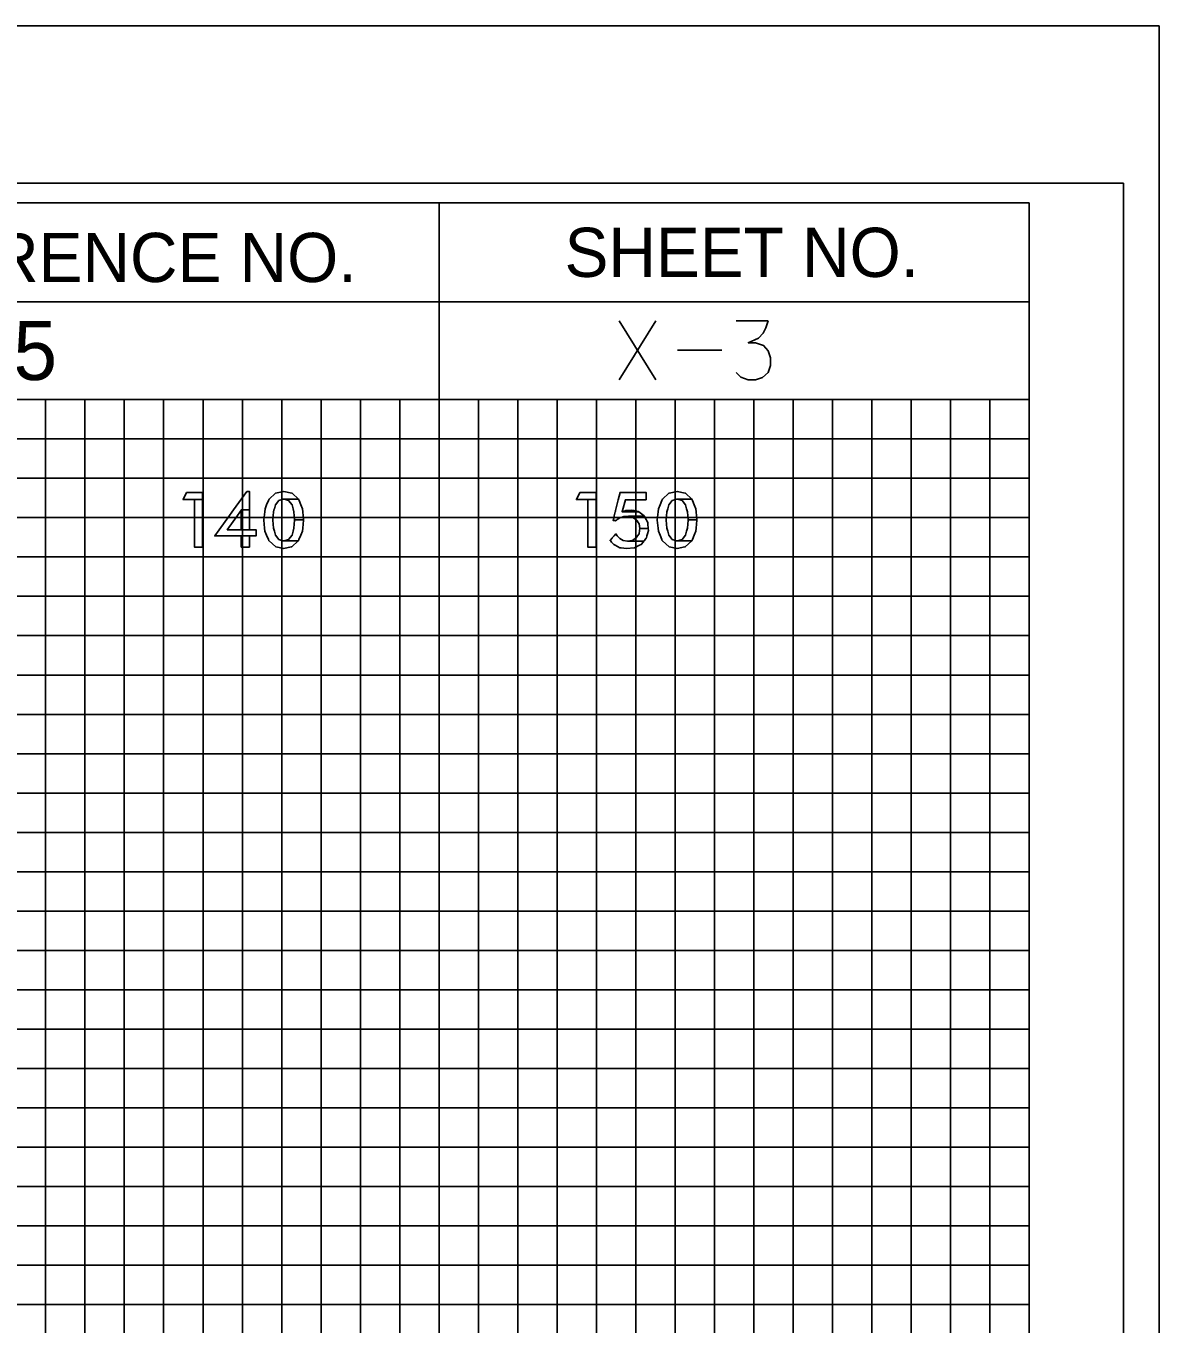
# Model space of a CAD drawing. Extents: x -13 to 323, y -5 to 1431.
# Drawn here: x 294.5 to 323.3, y 401.5 to 434.5 of the extents above; entities that cross this region are included whole.
import ezdxf

# ---------------------------------------------------------------- set-up
doc = ezdxf.new("R2010")
doc.units = 0
for name, color, linetype in [('Prop XS Offset Labels', 7, 'Continuous'), ('Prop XS Project Number', 7, 'Continuous'), ('Prop XS Sheet Number', 7, 'Continuous'), ('Sheet Cross Section CELL', 7, 'Continuous'), ('Sheet Cross Section Grid Major CELL', 7, 'Continuous'), ('Sheet Cross Section Grid Middle CELL', 7, 'Continuous'), ('Sheet Cross Section Grid Minor 1 CELL', 7, 'Continuous'), ('Sheet Cross Section Grid Minor 2 CELL', 7, 'Continuous'), ('Sheet Cutting Line CELL', 7, 'Continuous'), ('Sheet DOT Grid CELL', 7, 'Continuous'), ('Sheet Plot Border Inside CELL', 7, 'Continuous'), ('Sheet Plot Border Outside CELL', 7, 'Continuous')]:
    doc.layers.add(name, color=color, linetype=linetype)

msp = doc.modelspace()

# ---------------------------------------------------------------- linework, layer by layer
at = {"layer": 'Prop XS Offset Labels'}
for points in [[(298.581, 422.641), (298.492, 422.459), (298.99, 422.459), (298.99, 422.641)], [(298.781, 422.459), (298.781, 421.25), (298.99, 421.25), (298.99, 422.459)], [(299.411, 421.693), (299.297, 421.534), (300.35, 421.534), (300.35, 421.693), (299.618, 421.693), (299.878, 422.059), (299.935, 422.139), (299.977, 422.199), (300.179, 422.199), (300.179, 422.668), (300.114, 422.668), (299.775, 422.199), (299.733, 422.139), (299.675, 422.059)], [(300.851, 421.255), (301.051, 421.214), (301.245, 421.255), (301.256, 421.257), (301.422, 421.409), (301.048, 421.409), (301.038, 421.411), (301.033, 421.413), (300.928, 421.442), (300.841, 421.555), (300.841, 421.556), (300.841, 421.556), (300.813, 421.657), (300.813, 421.659), (300.793, 421.732), (300.792, 421.736), (300.774, 421.939), (300.774, 421.941), (300.774, 421.943), (300.792, 422.145), (300.812, 422.222), (300.813, 422.224), (300.839, 422.322), (300.84, 422.325), (300.928, 422.44), (301.041, 422.469), (301.045, 422.47), (301.055, 422.473), (301.425, 422.473), (301.262, 422.622), (301.254, 422.624), (301.053, 422.668), (301.053, 422.668), (300.845, 422.624), (300.843, 422.622), (300.681, 422.473), (300.678, 422.47), (300.678, 422.469), (300.665, 422.44), (300.618, 422.325), (300.617, 422.322), (300.577, 422.224), (300.576, 422.222), (300.568, 422.145), (300.547, 421.943), (300.547, 421.941), (300.547, 421.939), (300.567, 421.736), (300.567, 421.732), (300.575, 421.659), (300.575, 421.657), (300.616, 421.556), (300.617, 421.555), (300.663, 421.442), (300.675, 421.413), (300.676, 421.411), (300.679, 421.409), (300.848, 421.257)], [(301.312, 422.145), (301.328, 421.943), (301.555, 421.943), (301.536, 422.145), (301.528, 422.222), (301.528, 422.224), (301.527, 422.224), (301.488, 422.322), (301.488, 422.322), (301.487, 422.325), (301.441, 422.44), (301.44, 422.44), (301.429, 422.469), (301.428, 422.47), (301.425, 422.473), (301.055, 422.473), (301.065, 422.47), (301.068, 422.469), (301.175, 422.44), (301.262, 422.325), (301.265, 422.322), (301.291, 422.224), (301.291, 422.222)], [(308.581, 422.641), (308.492, 422.459), (308.99, 422.459), (308.99, 422.641)], [(308.781, 422.459), (308.781, 421.25), (308.99, 421.25), (308.99, 422.459)], [(309.427, 421.94), (309.424, 421.928), (309.495, 421.928), (309.508, 421.94), (309.524, 421.954), (309.595, 421.997), (309.627, 422.007), (309.697, 422.029), (309.811, 422.035), (310.219, 422.035), (310.211, 422.05), (310.076, 422.145), (309.655, 422.145), (309.658, 422.158), (309.658, 422.158), (309.663, 422.178), (309.738, 422.456), (310.263, 422.456), (310.263, 422.641), (309.6, 422.641), (309.554, 422.456), (309.486, 422.178), (309.481, 422.158), (309.478, 422.145), (309.454, 422.05), (309.451, 422.035), (309.449, 422.029), (309.444, 422.007), (309.441, 421.997), (309.431, 421.954)], [(310.851, 421.255), (311.051, 421.214), (311.245, 421.255), (311.256, 421.257), (311.422, 421.409), (311.048, 421.409), (311.038, 421.411), (311.033, 421.413), (310.928, 421.442), (310.841, 421.555), (310.841, 421.556), (310.841, 421.556), (310.813, 421.657), (310.813, 421.659), (310.793, 421.732), (310.792, 421.736), (310.774, 421.939), (310.774, 421.941), (310.774, 421.943), (310.792, 422.145), (310.812, 422.222), (310.813, 422.224), (310.839, 422.322), (310.84, 422.325), (310.928, 422.44), (311.041, 422.469), (311.045, 422.47), (311.055, 422.473), (311.425, 422.473), (311.262, 422.622), (311.254, 422.624), (311.053, 422.668), (311.053, 422.668), (310.845, 422.624), (310.843, 422.622), (310.681, 422.473), (310.678, 422.47), (310.678, 422.469), (310.665, 422.44), (310.618, 422.325), (310.617, 422.322), (310.577, 422.224), (310.576, 422.222), (310.568, 422.145), (310.547, 421.943), (310.547, 421.941), (310.547, 421.939), (310.567, 421.736), (310.567, 421.732), (310.575, 421.659), (310.575, 421.657), (310.616, 421.556), (310.617, 421.555), (310.663, 421.442), (310.675, 421.413), (310.676, 421.411), (310.679, 421.409), (310.848, 421.257)], [(311.312, 422.145), (311.328, 421.943), (311.555, 421.943), (311.536, 422.145), (311.528, 422.222), (311.528, 422.224), (311.527, 422.224), (311.488, 422.322), (311.488, 422.322), (311.487, 422.325), (311.441, 422.44), (311.44, 422.44), (311.429, 422.469), (311.428, 422.47), (311.425, 422.473), (311.055, 422.473), (311.065, 422.47), (311.068, 422.469), (311.175, 422.44), (311.262, 422.325), (311.265, 422.322), (311.291, 422.224), (311.291, 422.222)], [(299.97, 422.059), (299.97, 421.693), (300.179, 421.693), (300.179, 422.059), (300.179, 422.139), (300.179, 422.199), (299.977, 422.199), (299.973, 422.139)], [(309.692, 422.158), (309.655, 422.145), (310.076, 422.145), (310.058, 422.158), (309.961, 422.178), (309.75, 422.178)], [(309.888, 422.192), (309.75, 422.178), (309.96, 422.178), (309.888, 422.192)], [(301.058, 421.411), (301.048, 421.409), (301.422, 421.409), (301.425, 421.411), (301.426, 421.413), (301.438, 421.442), (301.485, 421.555), (301.485, 421.556), (301.527, 421.657), (301.528, 421.659), (301.535, 421.732), (301.535, 421.736), (301.555, 421.939), (301.556, 421.941), (301.555, 421.943), (301.328, 421.943), (301.328, 421.941), (301.328, 421.939), (301.312, 421.736), (301.312, 421.732), (301.292, 421.659), (301.291, 421.657), (301.264, 421.556), (301.263, 421.555), (301.175, 421.442), (301.063, 421.413)], [(309.424, 421.928), (309.482, 421.916), (309.495, 421.928)], [(310.083, 421.841), (310.105, 421.721), (310.318, 421.721), (310.307, 421.841), (310.307, 421.841), (310.303, 421.881), (310.284, 421.916), (310.278, 421.928), (310.271, 421.94), (310.263, 421.954), (310.24, 421.997), (310.235, 422.007), (310.223, 422.029), (310.219, 422.035), (309.811, 422.035), (309.838, 422.029), (309.928, 422.007), (309.942, 421.997), (310.003, 421.954), (310.024, 421.94), (310.031, 421.928), (310.038, 421.916), (310.059, 421.881)], [(311.058, 421.411), (311.048, 421.409), (311.422, 421.409), (311.425, 421.411), (311.426, 421.413), (311.438, 421.442), (311.485, 421.555), (311.485, 421.556), (311.527, 421.657), (311.528, 421.659), (311.535, 421.732), (311.535, 421.736), (311.555, 421.939), (311.556, 421.941), (311.555, 421.943), (311.328, 421.943), (311.328, 421.941), (311.328, 421.939), (311.312, 421.736), (311.312, 421.732), (311.292, 421.659), (311.291, 421.657), (311.264, 421.556), (311.263, 421.555), (311.175, 421.442), (311.063, 421.413)], [(299.97, 421.534), (299.97, 421.25), (300.179, 421.25), (300.179, 421.534)], [(309.626, 421.233), (309.762, 421.214), (309.959, 421.233), (309.968, 421.237), (310.091, 421.297), (310.091, 421.297), (310.141, 421.321), (310.185, 421.375), (310.204, 421.399), (309.793, 421.399), (309.683, 421.418), (309.682, 421.419), (309.679, 421.42), (309.596, 421.466), (309.586, 421.477), (309.58, 421.483), (309.58, 421.483), (309.529, 421.535), (309.497, 421.585), (309.497, 421.585), (309.451, 421.535), (309.404, 421.483), (309.399, 421.477), (309.39, 421.466), (309.348, 421.42), (309.347, 421.419), (309.348, 421.418), (309.363, 421.399), (309.382, 421.375), (309.445, 421.321), (309.474, 421.297), (309.598, 421.237)], [(309.9, 421.418), (309.793, 421.399), (310.204, 421.399), (310.22, 421.418), (310.221, 421.419), (310.222, 421.42), (310.222, 421.42), (310.259, 421.466), (310.268, 421.477), (310.27, 421.483), (310.284, 421.535), (310.299, 421.59), (310.322, 421.674), (310.318, 421.721), (310.105, 421.721), (310.097, 421.674), (310.082, 421.59), (310.047, 421.535), (310.014, 421.483), (310.004, 421.477), (309.987, 421.466), (309.913, 421.42), (309.905, 421.419)]]:
    msp.add_lwpolyline(points, close=True, dxfattribs=at)
at = {"layer": 'Prop XS Sheet Number'}
for p, q in [((309.575, 427), (310.508, 425.5)), ((310.508, 427), (309.575, 425.5)), ((312.551, 427), (313.366, 427)), ((311.063, 426.256), (312.185, 426.256))]:
    msp.add_line(p, q, dxfattribs=at)
msp.add_lwpolyline([(313.366, 427), (313.307, 426.823), (313.236, 426.693), (313.118, 426.563), (312.858, 426.445), (313.047, 426.445), (313.248, 426.374), (313.366, 426.244), (313.425, 426.067), (313.425, 425.866), (313.366, 425.689), (313.224, 425.559), (313.047, 425.5), (312.858, 425.5), (312.669, 425.571), (312.551, 425.689)], dxfattribs=at)
at = {"layer": 'Sheet Cross Section CELL'}
for p, q in [((305, 430), (305, 425)), ((305, 425), (305, 430)), ((320, 427.49), (280, 427.49)), ((280, 425), (320, 425))]:
    msp.add_line(p, q, dxfattribs=at)
for points in [[(320, 430), (0, 430), (0, 220), (320, 220)], [(320, 430), (280, 430), (280, 425), (320, 425)]]:
    msp.add_lwpolyline(points, close=True, dxfattribs=at)
at = {"layer": 'Sheet Cross Section Grid Major CELL'}
for p, q in [((310, 425), (300, 425)), ((300, 425), (300, 220)), ((310, 220), (310, 425))]:
    msp.add_line(p, q, dxfattribs=at)
msp.add_lwpolyline([(0, 420), (320, 420), (320, 410), (0, 410)], dxfattribs=at)
at = {"layer": 'Sheet Cross Section Grid Middle CELL'}
for points in [[(295, 220), (295, 425), (305, 425), (305, 220)], [(315, 220), (315, 425)], [(0, 405), (320, 405), (320, 415), (0, 415)]]:
    msp.add_lwpolyline(points, dxfattribs=at)
at = {"layer": 'Sheet Cross Section Grid Minor 1 CELL'}
msp.add_line((0, 424), (320, 424), dxfattribs=at)
for points in [[(0, 423), (270, 423), (320, 423), (320, 422), (0, 422)], [(0, 421), (320, 421), (320, 419), (0, 419)], [(0, 418), (320, 418), (320, 417), (0, 416.98)], [(0, 416), (320, 416), (320, 414), (0, 414)], [(0, 413), (320, 413), (320, 412), (0, 412)], [(0, 411), (320, 411), (320, 409), (0, 409)], [(0, 408), (320, 408), (320, 407), (0, 407)], [(0, 406), (320, 406), (320, 404), (0, 404)], [(0, 403), (320, 403), (320, 402), (0, 402)]]:
    msp.add_lwpolyline(points, dxfattribs=at)
at = {"layer": 'Sheet Cross Section Grid Minor 2 CELL'}
for points in [[(295, 220), (296, 220), (296, 425), (297, 425), (297, 220)], [(297, 220), (298, 220), (298, 425), (299, 425), (299, 220)], [(300, 220), (301, 220), (301, 425), (302, 425), (302, 220)], [(302, 220), (303, 220), (303, 425), (304, 425), (304, 220)], [(305, 220), (306, 220), (306, 425), (307, 425), (307, 220)], [(307, 220), (308, 220), (308, 425), (309, 425), (309, 220)], [(310, 220), (311, 220), (311, 425), (312, 425), (312, 220)], [(312, 220), (313, 220), (313, 425), (314, 425), (314, 220)], [(315, 220), (316, 220), (316, 425), (317, 425), (317, 220)], [(317, 220), (318, 220), (318, 425), (319, 425), (319, 220)]]:
    msp.add_lwpolyline(points, dxfattribs=at)
at = {"layer": 'Sheet Cutting Line CELL'}
msp.add_line((323.3, 434.5), (-13.4, 434.5), dxfattribs=at)
at = {"layer": 'Sheet DOT Grid CELL'}
for p, q in [((300, 220), (300, 424.687)), ((310, 220), (310, 424.687)), ((0, 420), (320, 420)), ((0, 410), (320, 410))]:
    msp.add_line(p, q, dxfattribs=at)
at = {"layer": 'Sheet Plot Border Inside CELL'}
msp.add_lwpolyline([(-10.8, 219.5), (322.4, 219.5), (322.4, 430.5), (-10.8, 430.5)], close=True, dxfattribs=at)
at = {"layer": 'Sheet Plot Border Outside CELL'}
msp.add_lwpolyline([(-13.4, 215.5), (323.3, 215.5), (323.3, 434.5), (-13.4, 434.5)], close=True, dxfattribs=at)

# ---------------------------------------------------------------- texts
at = {"layer": 'Prop XS Project Number'}
msp.add_text('HL-0025', height=1.5, dxfattribs=at).set_placement((287.598, 425.5))
at = {"layer": 'Sheet Cross Section CELL'}
for s, height, p in [('SHEET NO.', 1.25, (308.19, 428.12)), ('PROJ. REFERENCE NO.', 1.24998, (283.77, 427.99))]:
    msp.add_text(s, height=height, dxfattribs=at).set_placement(p)

doc.saveas('drawing.dxf')
